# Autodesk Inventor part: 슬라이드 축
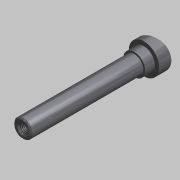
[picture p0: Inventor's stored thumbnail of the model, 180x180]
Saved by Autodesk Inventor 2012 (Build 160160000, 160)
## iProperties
Company: 한국ATC센터
Created: 2014-07
Part Number: 슬라이드 축
Document SubType Name: 모델링
Designer: KYOUNG IL JANG
Mass: 169.556 g
Surface Area: 67.5855 cm^2
Volume: 21.572 cm^3
Density: 7.86 g/cm^3
Material: 강, 연강
변환 표준: STEP AP214IS
파일 이름: C:\Users\SeoGD\Desktop\?쒗뿕\異?stp
전처리기: Build: 253, Release: 2010 SP1 - Date: Wed 07/29/2009
전송 단위: 밀리미터
불확실성: 0.01
Author: KYOUNG IL JANG
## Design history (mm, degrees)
sketch "스케치1"
  geometry: L1 (0, 100)-(7.5, 100); L2 (7.5, 100)-(7.5, 0); L3 (7.5, 0)-(12.5, 0); L4 (12.5, 0)-(12.5, -17); L5 (12.5, -17)-(0, -17); L6 (0, -17)-(0, 100); 1 further point
  constraints: 12 end point, 2 parallel, 2 point on line, 1 perpendicular, 1 vertical
  dimensions: "d0" = 100 distance from line of L1 point (0, 0); "d1" = 15 diameter of L2 L6; "d2" = 25 diameter of L4 L6; "d3" = 17 distance of L3.end L4.end
revolve "회전1" sketch "스케치1" stored, may be unused: angle "d4" = 90 deg
sketch "스케치2"
  geometry: L1 (12.5, 0)-(12.5, -17) reference; L2 (-12.5, -17)-(12.5, -17) reference; L3 (-12.5, 0)-(-12.5, -17) reference; L4 (12.5, -5)-(-12.5, -11.699); L5 (-12.5, 0)-(12.5, 0) reference; 1 further point
  constraints: 2 end point, 2 point on line
  dimensions: "d5" = 75 deg angle of L1 L4; "d6" = 5 distance from line of L4.start L5
extrude "돌출1" cut sketch "스케치2" stored distance "d7" = 10; taper "d8" = 0 deg
chamfer "모따기1" distance "d9" = 1; stored, may be unused: second distance "d10" = 2, angle "d11" = 45 deg
fillet "모깎기1" dims "d12" = 0.5
hole "구멍1" diameter "d15" = 6.647; stored, may be unused: countersink angle "d19" = 90 deg, drill point angle "d21" = 118 deg; dims "d13" = 10, "d14" = 10, "d16" = 17, "d17" = 4, "d18" = 2, "d20" = 20
chamfer "모따기2" distance "d22" = 1; stored, may be unused: second distance "d23" = 2, angle "d24" = 45 deg
sketch "스케치3"
  geometry: C1 r 9 at (0, 0); 1 further point
  constraints: 1 centre point, 1 coincident
  dimensions: "d25" = 18 diameter of C1
extrude "돌출2" join sketch "스케치3" distance "d26" = 8; taper "d27" = 0 deg
node "솔리드1"
node "솔리드 본체"
node "곡면 본체"
node "솔리드2"
